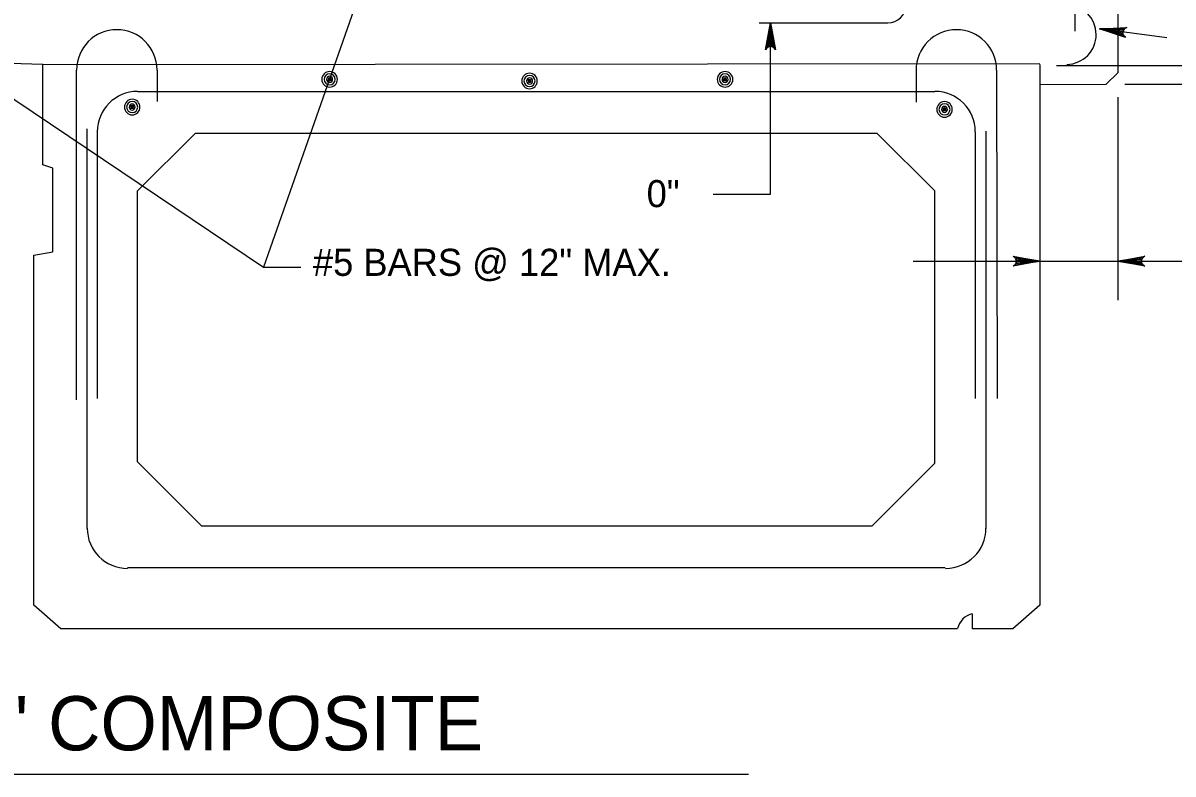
# Model space of a CAD drawing. Extents: x 639331 to 643089, y 299088 to 300975.
# Drawn here: x 641557.2 to 641684.5, y 299989.8 to 300072.9 of the extents above; entities that cross this region are included whole.
import ezdxf

# ---------------------------------------------------------------- set-up
doc = ezdxf.new("R2010")
doc.units = 0
doc.layers.add('1', color=7, linetype='Continuous')

msp = doc.modelspace()

# ---------------------------------------------------------------- linework, layer by layer
at = {"layer": '1'}
for p, q in [((641673.65, 300072.04), (641673.65, 300126.04)), ((641601.78, 300097.16), (641583.83, 300045.88)), ((641516.83, 300090.97), (641583.83, 300045.88)), ((641678.38, 300084.36), (641678.38, 300067.43)), ((641638.68, 300072.93), (641652.92, 300072.93)), ((641639.94, 300053.99), (641639.94, 300072.93)), ((641683.79, 300071.29), (641676.35, 300072.29)), ((641559.38, 300068.34), (641555.78, 300068.45)), ((641559.38, 300068.34), (641669.75, 300068.45)), ((641559.38, 300057.21), (641559.38, 300068.34)), ((641563.13, 300031.21), (641563.13, 300067.72)), ((641572.04, 300067.72), (641572.03, 300064.25)), ((641656.05, 300067.72), (641656.04, 300064.18)), ((641664.95, 300067.72), (641665, 300031.34)), ((641669.75, 300068.34), (641669.75, 300008.46)), ((641671.59, 300068.21), (641688.45, 300068.21)), ((641591.66, 300066.84), (641591.66, 300066.84)), ((641612.73, 300066.66), (641612.73, 300066.66)), ((641613.37, 300066.72), (641613.37, 300066.72)), ((641634.37, 300066.84), (641634.37, 300066.84)), ((641677.09, 300066.14), (641678.38, 300067.43)), ((641569.88, 300065.34), (641658.13, 300065.34)), ((641669.75, 300066.13), (641677.09, 300066.14)), ((641679.13, 300066.14), (641688.45, 300066.14)), ((641569.43, 300063.94), (641569.43, 300063.94)), ((641678.38, 300064.7), (641678.38, 300042.26)), ((641658.66, 300063.52), (641658.66, 300063.52)), ((641659.64, 300063.33), (641659.64, 300063.33)), ((641564.25, 300061.21), (641564.25, 300016.96)), ((641565.42, 300060.89), (641565.42, 300031.34)), ((641576.25, 300060.71), (641569.88, 300054.34)), ((641651.75, 300060.71), (641576.25, 300060.71)), ((641658.13, 300054.34), (641651.75, 300060.71)), ((641662.58, 300060.89), (641662.58, 300031.34)), ((641663.75, 300060.96), (641663.75, 300016.96)), ((641560.5, 300056.84), (641559.38, 300057.21)), ((641560.5, 300047.59), (641560.5, 300056.84)), ((641569.88, 300024.34), (641569.88, 300054.34)), ((641633.58, 300053.99), (641639.94, 300053.99)), ((641658.13, 300024.21), (641658.13, 300054.34)), ((641558.38, 300047.21), (641560.5, 300047.59)), ((641558.38, 300008.46), (641558.38, 300047.21)), ((641655.71, 300046.55), (641669.75, 300046.55)), ((641669.75, 300046.55), (641678.38, 300046.55)), ((641678.38, 300046.55), (641685.92, 300046.55)), ((641583.83, 300045.88), (641587.93, 300045.88)), ((641577, 300017.21), (641569.88, 300024.34)), ((641658.13, 300024.21), (641651.13, 300017.21)), ((641651.13, 300017.21), (641577, 300017.21)), ((641659.25, 300012.59), (641568.75, 300012.59)), ((641561.38, 300005.84), (641558.38, 300008.46)), ((641669.75, 300008.46), (641666.75, 300005.84)), ((641662.25, 300007.46), (641662.25, 300005.84)), ((641660.63, 300005.84), (641561.38, 300005.84)), ((641666.75, 300005.84), (641662.25, 300005.84)), ((641521.95, 299989.78), (641637.48, 299989.78))]:
    msp.add_line(p, q, dxfattribs=at)
for points in [[(641639.94, 300072.93), (641640.5, 300069.95), (641640.42, 300070.06), (641640.34, 300070.18), (641640.24, 300070.24), (641640.14, 300070.3), (641640.04, 300070.31), (641639.94, 300070.33), (641639.84, 300070.31), (641639.74, 300070.3), (641639.64, 300070.24), (641639.54, 300070.18), (641639.46, 300070.06), (641639.38, 300069.95), (641639.94, 300072.93), (641639.46, 300070.06), (641639.54, 300070.18), (641639.94, 300072.93), (641639.64, 300070.24), (641639.74, 300070.3), (641639.94, 300072.93), (641639.84, 300070.31), (641639.94, 300070.33), (641639.94, 300072.93), (641640.04, 300070.31), (641640.14, 300070.3), (641639.94, 300072.93), (641640.24, 300070.24), (641640.34, 300070.18), (641639.94, 300072.93), (641640.42, 300070.06)], [(641676.35, 300072.29), (641679.38, 300072.44), (641679.26, 300072.38), (641679.13, 300072.32), (641679.06, 300072.23), (641678.99, 300072.13), (641678.96, 300072.04), (641678.93, 300071.94), (641678.93, 300071.84), (641678.93, 300071.74), (641678.98, 300071.63), (641679.02, 300071.52), (641679.13, 300071.43), (641679.23, 300071.34), (641676.35, 300072.29), (641679.13, 300071.43), (641679.02, 300071.52), (641676.35, 300072.29), (641678.98, 300071.63), (641678.93, 300071.74), (641676.35, 300072.29), (641678.93, 300071.84), (641678.93, 300071.94), (641676.35, 300072.29), (641678.96, 300072.04), (641678.99, 300072.13), (641676.35, 300072.29), (641679.06, 300072.23), (641679.13, 300072.32), (641676.35, 300072.29), (641679.26, 300072.38)], [(641669.75, 300046.55), (641666.77, 300045.99), (641666.88, 300046.07), (641667, 300046.15), (641667.06, 300046.25), (641667.12, 300046.35), (641667.13, 300046.45), (641667.15, 300046.55), (641667.13, 300046.65), (641667.12, 300046.75), (641667.06, 300046.85), (641667, 300046.95), (641666.88, 300047.03), (641666.77, 300047.11), (641669.75, 300046.55), (641666.88, 300047.03), (641667, 300046.95), (641669.75, 300046.55), (641667.06, 300046.85), (641667.12, 300046.75), (641669.75, 300046.55), (641667.13, 300046.65), (641667.15, 300046.55), (641669.75, 300046.55), (641667.13, 300046.45), (641667.12, 300046.35), (641669.75, 300046.55), (641667.06, 300046.25), (641667, 300046.15), (641669.75, 300046.55), (641666.88, 300046.07)], [(641678.38, 300046.55), (641681.36, 300047.11), (641681.24, 300047.03), (641681.13, 300046.95), (641681.07, 300046.85), (641681.01, 300046.75), (641680.99, 300046.65), (641680.98, 300046.55), (641680.99, 300046.45), (641681.01, 300046.35), (641681.07, 300046.25), (641681.13, 300046.15), (641681.24, 300046.07), (641681.36, 300045.99), (641678.38, 300046.55), (641681.24, 300046.07), (641681.13, 300046.15), (641678.38, 300046.55), (641681.07, 300046.25), (641681.01, 300046.35), (641678.38, 300046.55), (641680.99, 300046.45), (641680.98, 300046.55), (641678.38, 300046.55), (641680.99, 300046.65), (641681.01, 300046.75), (641678.38, 300046.55), (641681.07, 300046.85), (641681.13, 300046.95), (641678.38, 300046.55), (641681.24, 300047.03)]]:
    msp.add_lwpolyline(points, dxfattribs=at)
for centre, radius, start, end in [((641652.92, 300074.93), 2, 270, 0), ((641672.69, 300071.64), 3.29, 270.6257, 89.91), ((641567.58, 300067.72), 4.46, 90, 180), ((641567.58, 300067.72), 4.46, 0, 90), ((641660.5, 300067.72), 4.46, 90, 180.0003), ((641660.5, 300067.72), 4.46, 0, 90), ((641591.13, 300066.69), 0.861, 0, 180), ((641591.13, 300066.69), 0.861, 180, 0), ((641591.13, 300066.69), 0.614, 0, 180), ((641591.13, 300066.69), 0.614, 180, 0), ((641591.13, 300066.69), 0.336, 0, 180), ((641591.13, 300066.69), 0.336, 180, 0), ((641591.13, 300066.69), 0.17, 0, 180), ((641591.13, 300066.69), 0.17, 180, 0), ((641591.13, 300066.69), 0.0726, 0, 180), ((641591.13, 300066.69), 0.0726, 180, 0), ((641613.26, 300066.51), 0.861, 0, 180), ((641613.26, 300066.51), 0.861, 180, 0), ((641613.26, 300066.51), 0.614, 0, 180), ((641613.26, 300066.51), 0.614, 180, 0), ((641613.26, 300066.51), 0.336, 0, 180), ((641613.26, 300066.51), 0.336, 180, 0), ((641613.26, 300066.51), 0.17, 0, 180), ((641613.26, 300066.51), 0.17, 180, 0), ((641613.26, 300066.51), 0.0726, 0, 180), ((641613.26, 300066.51), 0.0726, 180, 0), ((641634.9, 300066.69), 0.861, 0, 180), ((641634.9, 300066.69), 0.861, 180, 0), ((641634.9, 300066.69), 0.614, 0, 180), ((641634.9, 300066.69), 0.614, 180, 0), ((641634.9, 300066.69), 0.336, 0, 180), ((641634.9, 300066.69), 0.336, 180, 0), ((641634.9, 300066.69), 0.17, 0, 180), ((641634.9, 300066.69), 0.17, 180, 0), ((641634.9, 300066.69), 0.0726, 0, 180), ((641634.9, 300066.69), 0.0726, 180, 0), ((641569.88, 300060.89), 4.46, 90, 180), ((641658.13, 300060.89), 4.46, 0, 90), ((641569.28, 300063.62), 0.861, 0, 180), ((641569.28, 300063.62), 0.614, 0, 180), ((641569.28, 300063.62), 0.336, 0, 180), ((641659.19, 300063.36), 0.861, 0, 180), ((641659.19, 300063.36), 0.614, 0, 180), ((641569.28, 300063.62), 0.861, 180, 0), ((641569.28, 300063.62), 0.614, 180, 0), ((641569.28, 300063.62), 0.336, 180, 0), ((641569.28, 300063.62), 0.17, 0, 180), ((641569.28, 300063.62), 0.17, 180, 0), ((641569.28, 300063.62), 0.0726, 0, 180), ((641569.28, 300063.62), 0.0726, 180, 0), ((641659.19, 300063.36), 0.861, 180, 0), ((641659.19, 300063.36), 0.614, 180, 0), ((641659.19, 300063.36), 0.336, 0, 180), ((641659.19, 300063.36), 0.336, 180, 0), ((641659.19, 300063.36), 0.17, 0, 180), ((641659.19, 300063.36), 0.17, 180, 0), ((641659.19, 300063.36), 0.0726, 0, 180), ((641659.19, 300063.36), 0.0726, 180, 0), ((641568.76, 300017), 4.46, 180, 270), ((641659.31, 300017), 4.46, 270, 0), ((641662.72, 300005.42), 2.14, 101.5949, 167.5435)]:
    msp.add_arc(centre, radius, start, end, dxfattribs=at)

# ---------------------------------------------------------------- texts
for s, height, p in [('0"', 3, (641626.22, 300052.54)), ('#5 BARS @ 12" MAX.', 3, (641589.29, 300044.93)), ('36" & 48" COMPOSITE', 6, (641524.39, 299992.4))]:
    msp.add_text(s, height=height, dxfattribs=at).set_placement(p)

doc.saveas('drawing.dxf')
